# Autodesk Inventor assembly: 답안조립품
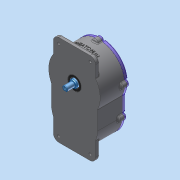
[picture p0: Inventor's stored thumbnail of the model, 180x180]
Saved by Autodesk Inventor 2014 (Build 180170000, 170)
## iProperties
Created: 2025-09
Part Number: 답안조립품
Document SubType Name: Assembly
Designer: dg
Author: dg
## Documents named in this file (19)
- C:\Users\dg\Desktop\750903V1005\답안조립품.iam
- C:\Users\dg\Desktop\750903V1005\본체.ipt
- C:\Users\dg\Desktop\750903V1005\가져온 구성요소\구동 축\구동 축.ipt
- C:\Users\dg\Desktop\750903V1005\가져온 구성요소\깊은 홈 볼 베어링 6904\깊은 홈 볼 베어링 6904.ipt
- C:\Users\dg\Desktop\750903V1005\가져온 구성요소\오일 실 20 35 8\오일 실 20 35 8.ipt
- C:\Users\dg\Desktop\750903V1005\가져온 구성요소\구동 휠\구동 휠.ipt
- C:\Users\dg\Desktop\750903V1005\가져온 구성요소\칼라\칼라.ipt
- C:\Users\dg\Desktop\750903V1005\가져온 구성요소\평행 키 6x6x14\평행 키 6x6x14.ipt
- C:\Users\dg\Desktop\750903V1005\가져온 구성요소\6각 구멍붙이 볼트 M6x12\6각 구멍붙이 볼트 M6x12.ipt
- C:\Users\dg\Desktop\750903V1005\가져온 구성요소\스러스트 볼 베어링 51102\스러스트 볼 베어링 51102.ipt
- C:\Users\dg\Desktop\750903V1005\가져온 구성요소\어댑터\어댑터.ipt
- C:\Users\dg\Desktop\750903V1005\가져온 구성요소\슬롯 축\슬롯 축.ipt
- C:\Users\dg\Desktop\750903V1005\가져온 구성요소\슬롯\슬롯.ipt
- C:\Users\dg\Desktop\750903V1005\가져온 구성요소\스프링 와셔 M3\스프링 와셔 M3.ipt
- C:\Users\dg\Desktop\750903V1005\가져온 구성요소\육각 너트 M3\육각 너트 M3.ipt
- C:\Users\dg\Desktop\750903V1005\가져온 구성요소\캠 플로워\캠 플로워.ipt
- C:\Users\dg\Desktop\750903V1005\가져온 구성요소\평 와셔 M3\평 와셔 M3.ipt
- C:\Users\dg\Desktop\750903V1005\가져온 구성요소\커버\커버.ipt
- C:\Users\dg\Desktop\750903V1005\가져온 구성요소\6각 구멍붙이 볼트 M4x10\6각 구멍붙이 볼트 M4x10.ipt
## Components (9 placed, 4 different names)
1. 구동 축:1
2. 구동 휠:1
3. 6각 구멍붙이 볼트 M6x12:1
4. 6각 구멍붙이 볼트 M4x10:1
5. 6각 구멍붙이 볼트 M4x10:2
6. 6각 구멍붙이 볼트 M4x10:3
7. 6각 구멍붙이 볼트 M4x10:4
8. 6각 구멍붙이 볼트 M4x10:5
9. 6각 구멍붙이 볼트 M4x10:6
